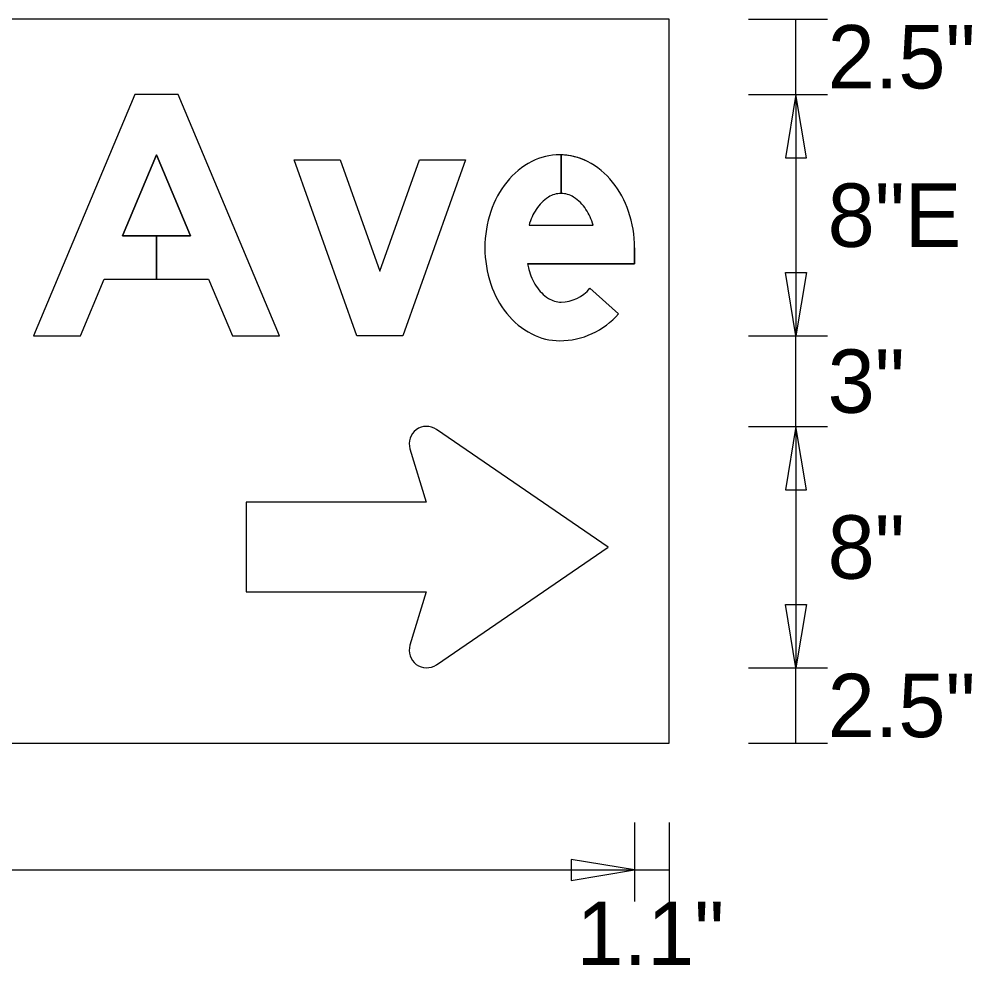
# Model space of a CAD drawing. Extents: x 1374 to 1480, y 568 to 638.
# Drawn here: x 1422.063 to 1424.694, y 629.461 to 632.074 of the extents above; entities that cross this region are included whole.
import ezdxf

# ---------------------------------------------------------------- set-up
doc = ezdxf.new("R2010")
doc.units = 0
for name, color, linetype in [('GSBWFill', 7, 'Continuous'), ('GSColorFill', 7, 'Continuous'), ('GSDims', 7, 'Continuous'), ('GSOutline', 7, 'Continuous')]:
    doc.layers.add(name, color=color, linetype=linetype)

msp = doc.modelspace()

# ---------------------------------------------------------------- linework, layer by layer
at = {"layer": 'GSBWFill'}
for p, q in [((1423.8581, 632.074), (1414.8581, 632.074)), ((1423.8581, 630.074), (1423.8581, 632.074)), ((1423.5594, 631.6989), (1423.5594, 631.5923)), ((1423.5594, 631.5923), (1423.5594, 631.6989)), ((1423.471, 631.5049), (1423.6478, 631.5049)), ((1423.6389, 631.3303), (1423.7184, 631.2601)), ((1414.8581, 630.074), (1423.8581, 630.074))]:
    msp.add_line(p, q, dxfattribs=at)
for points in [[(1422.5359, 631.4756), (1422.4423, 631.4756), (1422.4423, 631.3556), (1422.5863, 631.3556), (1422.6521, 631.199), (1422.7823, 631.199), (1422.5023, 631.8656), (1422.3823, 631.8656), (1422.1023, 631.199), (1422.2324, 631.199), (1422.2982, 631.3556), (1422.4423, 631.3556), (1422.4423, 631.4756), (1422.3486, 631.4756), (1422.4423, 631.6986)], [(1422.8223, 631.6856), (1422.9497, 631.6856), (1423.059, 631.3781), (1423.1683, 631.6856), (1423.2956, 631.6856), (1423.1226, 631.199), (1422.9953, 631.199)]]:
    msp.add_lwpolyline(points, close=True, dxfattribs=at)
for points in [[(1423.7623, 631.4423), (1423.7623, 631.3983), (1423.4665, 631.3983)], [(1423.2153, 630.2908), (1423.6899, 630.6157), (1423.2153, 630.9406)], [(1423.1421, 630.8868), (1423.1874, 630.7394), (1422.6899, 630.7394)], [(1422.6899, 630.7394), (1422.6899, 630.492), (1423.1874, 630.492), (1423.1421, 630.3446)]]:
    msp.add_lwpolyline(points, dxfattribs=at)
for centre, start, end in [((1423.1881, 630.9009), 55.6003, 197.0573), ((1423.1881, 630.3305), 162.9427, 304.3997)]:
    msp.add_arc(centre, 0.0481, start, end, dxfattribs=at)
for centre, major_axis, start_param, end_param in [((1423.5777, 631.4884), (0, 0.216), 0.475122, 0.892896), ((1423.5556, 631.5313), (0, 0.1677), 0, 0.475122), ((1423.5556, 631.5313), (0, 0.1677), 6.260763, 6.283185), ((1423.5556, 631.5313), (0, 0.1677), 5.808063, 6.260564), ((1423.5335, 631.4884), (0, 0.216), 5.390289, 5.808063), ((1423.6123, 631.4605), (0, 0.2604), 0.892896, 1.248875), ((1423.4989, 631.4605), (0, 0.2604), 5.03431, 5.390289), ((1423.5856, 631.487), (0, 0.113), 0.569258, 0.99633), ((1423.5594, 631.5279), (0, 0.0644), 0, 0.569258), ((1423.5594, 631.5279), (0, 0.0644), 5.713928, 6.282667), ((1423.5332, 631.487), (0, 0.113), 5.286855, 5.713928), ((1423.6273, 631.46), (0, 0.1627), 0.99633, 1.290964), ((1423.4915, 631.46), (0, 0.1627), 4.992222, 5.286855), ((1423.6668, 631.4423), (0, 0.3178), 1.248875, 1.570796), ((1423.4445, 631.4423), (0, 0.3178), 4.712389, 5.03431), ((1423.6668, 631.4423), (0, 0.3178), 1.570796, 1.892717), ((1423.6932, 631.4423), (0, 0.2309), 1.762764, 1.832751), ((1423.6273, 631.4246), (0, 0.1627), 1.832751, 2.145263), ((1423.6123, 631.4242), (0, 0.2604), 1.892717, 2.248697), ((1423.5856, 631.3977), (0, 0.113), 2.145263, 2.572335), ((1423.5594, 631.3946), (0, 0.1022), 3.141593, 4.032312), ((1423.5594, 631.3567), (0, 0.0644), 2.572335, 3.141593), ((1423.5777, 631.3963), (0, 0.216), 2.248697, 2.666471), ((1423.5556, 631.4007), (0, 0.2151), 3.141593, 3.999873), ((1423.5556, 631.3533), (0, 0.1677), 2.666471, 3.141593)]:
    msp.add_ellipse(centre, major_axis=major_axis, ratio=0.999992, start_param=start_param, end_param=end_param, dxfattribs=at)
at = {"layer": 'GSColorFill'}
for p, q in [((1423.8581, 632.074), (1414.8581, 632.074)), ((1423.8581, 632.074), (1414.8581, 632.074)), ((1423.8581, 630.074), (1423.8581, 632.074)), ((1423.8581, 630.074), (1423.8581, 632.074)), ((1423.5594, 631.6989), (1423.5594, 631.5923)), ((1423.5594, 631.5923), (1423.5594, 631.6989)), ((1423.471, 631.5049), (1423.6478, 631.5049)), ((1423.6389, 631.3303), (1423.7184, 631.2601)), ((1414.8581, 630.074), (1423.8581, 630.074)), ((1414.8581, 630.074), (1423.8581, 630.074))]:
    msp.add_line(p, q, dxfattribs=at)
for points in [[(1422.5359, 631.4756), (1422.4423, 631.4756), (1422.4423, 631.3556), (1422.5863, 631.3556), (1422.6521, 631.199), (1422.7823, 631.199), (1422.5023, 631.8656), (1422.3823, 631.8656), (1422.1023, 631.199), (1422.2324, 631.199), (1422.2982, 631.3556), (1422.4423, 631.3556), (1422.4423, 631.4756), (1422.3486, 631.4756), (1422.4423, 631.6986)], [(1422.8223, 631.6856), (1422.9497, 631.6856), (1423.059, 631.3781), (1423.1683, 631.6856), (1423.2956, 631.6856), (1423.1226, 631.199), (1422.9953, 631.199)]]:
    msp.add_lwpolyline(points, close=True, dxfattribs=at)
for points in [[(1423.7623, 631.4423), (1423.7623, 631.3983), (1423.4665, 631.3983)], [(1423.2153, 630.2908), (1423.6899, 630.6157), (1423.2153, 630.9406)], [(1423.1421, 630.8868), (1423.1874, 630.7394), (1422.6899, 630.7394)], [(1422.6899, 630.7394), (1422.6899, 630.492), (1423.1874, 630.492), (1423.1421, 630.3446)]]:
    msp.add_lwpolyline(points, dxfattribs=at)
for centre, start, end in [((1423.1881, 630.9009), 55.6003, 197.0573), ((1423.1881, 630.3305), 162.9427, 304.3997)]:
    msp.add_arc(centre, 0.0481, start, end, dxfattribs=at)
for centre, major_axis, start_param, end_param in [((1423.5777, 631.4884), (0, 0.216), 0.475122, 0.892896), ((1423.5556, 631.5313), (0, 0.1677), 0, 0.475122), ((1423.5556, 631.5313), (0, 0.1677), 6.260763, 6.283185), ((1423.5556, 631.5313), (0, 0.1677), 5.808063, 6.260564), ((1423.5335, 631.4884), (0, 0.216), 5.390289, 5.808063), ((1423.6123, 631.4605), (0, 0.2604), 0.892896, 1.248875), ((1423.4989, 631.4605), (0, 0.2604), 5.03431, 5.390289), ((1423.5856, 631.487), (0, 0.113), 0.569258, 0.99633), ((1423.5594, 631.5279), (0, 0.0644), 0, 0.569258), ((1423.5594, 631.5279), (0, 0.0644), 5.713928, 6.282667), ((1423.5332, 631.487), (0, 0.113), 5.286855, 5.713928), ((1423.6273, 631.46), (0, 0.1627), 0.99633, 1.290964), ((1423.4915, 631.46), (0, 0.1627), 4.992222, 5.286855), ((1423.6668, 631.4423), (0, 0.3178), 1.248875, 1.570796), ((1423.4445, 631.4423), (0, 0.3178), 4.712389, 5.03431), ((1423.6668, 631.4423), (0, 0.3178), 1.570796, 1.892717), ((1423.6932, 631.4423), (0, 0.2309), 1.762764, 1.832751), ((1423.6273, 631.4246), (0, 0.1627), 1.832751, 2.145263), ((1423.6123, 631.4242), (0, 0.2604), 1.892717, 2.248697), ((1423.5856, 631.3977), (0, 0.113), 2.145263, 2.572335), ((1423.5594, 631.3946), (0, 0.1022), 3.141593, 4.032312), ((1423.5594, 631.3567), (0, 0.0644), 2.572335, 3.141593), ((1423.5777, 631.3963), (0, 0.216), 2.248697, 2.666471), ((1423.5556, 631.4007), (0, 0.2151), 3.141593, 3.999873), ((1423.5556, 631.3533), (0, 0.1677), 2.666471, 3.141593)]:
    msp.add_ellipse(centre, major_axis=major_axis, ratio=0.999992, start_param=start_param, end_param=end_param, dxfattribs=at)
at = {"layer": 'GSDims'}
for p, q in [((1424.0769, 632.074), (1424.2956, 632.074)), ((1424.0769, 632.074), (1424.0769, 632.074)), ((1424.2081, 631.8656), (1424.2081, 632.074)), ((1424.0769, 631.8656), (1424.2956, 631.8656)), ((1424.0769, 631.8656), (1424.2956, 631.8656)), ((1424.2081, 631.8656), (1424.2081, 631.199)), ((1424.0769, 631.199), (1424.2956, 631.199)), ((1424.0769, 631.199), (1424.2956, 631.199)), ((1424.2081, 630.949), (1424.2081, 631.199)), ((1424.0769, 630.949), (1424.2956, 630.949)), ((1424.0769, 630.949), (1424.2956, 630.949)), ((1424.2081, 630.949), (1424.2081, 630.2824)), ((1424.0769, 630.2824), (1424.2956, 630.2824)), ((1424.0769, 630.2824), (1424.2956, 630.2824)), ((1424.2081, 630.074), (1424.2081, 630.2824)), ((1424.0769, 630.074), (1424.2956, 630.074)), ((1424.0769, 630.074), (1424.0769, 630.074)), ((1423.7623, 629.8552), (1423.7623, 629.6365)), ((1423.7623, 629.8552), (1423.7623, 629.6365)), ((1423.8581, 629.8552), (1423.8581, 629.6365)), ((1423.8581, 629.8552), (1423.8581, 629.6365)), ((1414.9553, 629.724), (1423.7623, 629.724)), ((1423.7623, 629.724), (1423.8581, 629.724))]:
    msp.add_line(p, q, dxfattribs=at)
for points in [[(1424.2081, 631.8656), (1424.179, 631.6906), (1424.2373, 631.6906)], [(1424.2081, 631.199), (1424.179, 631.374), (1424.2373, 631.374)], [(1424.2081, 630.949), (1424.179, 630.774), (1424.2373, 630.774)], [(1424.2081, 630.2824), (1424.179, 630.4574), (1424.2373, 630.4574)], [(1423.7623, 629.724), (1423.5873, 629.7531), (1423.5873, 629.6948)]]:
    msp.add_lwpolyline(points, close=True, dxfattribs=at)
at = {"layer": 'GSOutline'}
for p, q in [((1423.8581, 632.074), (1414.8581, 632.074)), ((1423.8581, 630.074), (1423.8581, 632.074)), ((1423.471, 631.5049), (1423.6478, 631.5049)), ((1423.7184, 631.2601), (1423.6389, 631.3303)), ((1414.8581, 630.074), (1423.8581, 630.074))]:
    msp.add_line(p, q, dxfattribs=at)
for points in [[(1422.2982, 631.3556), (1422.5863, 631.3556), (1422.6521, 631.199), (1422.7823, 631.199), (1422.5023, 631.8656), (1422.3823, 631.8656), (1422.1023, 631.199), (1422.2324, 631.199)], [(1422.5359, 631.4756), (1422.4423, 631.6986), (1422.3486, 631.4756)], [(1422.8223, 631.6856), (1422.9497, 631.6856), (1423.059, 631.3781), (1423.1683, 631.6856), (1423.2956, 631.6856), (1423.1226, 631.199), (1422.9953, 631.199)]]:
    msp.add_lwpolyline(points, close=True, dxfattribs=at)
for points in [[(1423.4665, 631.3983), (1423.7623, 631.3983), (1423.7623, 631.4423)], [(1423.2153, 630.2908), (1423.6899, 630.6157), (1423.2153, 630.9406)], [(1423.1421, 630.8868), (1423.1874, 630.7394), (1422.6899, 630.7394)], [(1422.6899, 630.7394), (1422.6899, 630.492), (1423.1874, 630.492), (1423.1421, 630.3446)]]:
    msp.add_lwpolyline(points, dxfattribs=at)
for centre, start, end in [((1423.1881, 630.9009), 55.6003, 197.0573), ((1423.1881, 630.3305), 162.9427, 304.3997)]:
    msp.add_arc(centre, 0.0481, start, end, dxfattribs=at)
for centre, major_axis, start_param, end_param in [((1423.5777, 631.4884), (0, 0.216), 0.475122, 0.892896), ((1423.5556, 631.5313), (0, 0.1677), 0, 0.475122), ((1423.5556, 631.5313), (0, 0.1677), 5.808063, 6.283185), ((1423.5335, 631.4884), (0, 0.216), 5.390289, 5.808063), ((1423.6123, 631.4605), (0, 0.2604), 0.892896, 1.248875), ((1423.4989, 631.4605), (0, 0.2604), 5.03431, 5.390289), ((1423.5856, 631.487), (0, 0.113), 0.569258, 0.99633), ((1423.5594, 631.5279), (0, 0.0644), 0, 0.569258), ((1423.5594, 631.5279), (0, 0.0644), 5.713928, 6.283185), ((1423.5332, 631.487), (0, 0.113), 5.286855, 5.713928), ((1423.6273, 631.46), (0, 0.1627), 0.99633, 1.290964), ((1423.4915, 631.46), (0, 0.1627), 4.992222, 5.286855), ((1423.6668, 631.4423), (0, 0.3178), 1.248875, 1.570796), ((1423.4445, 631.4423), (0, 0.3178), 4.712389, 5.03431), ((1423.6668, 631.4423), (0, 0.3178), 1.570796, 1.892717), ((1423.6932, 631.4423), (0, 0.2309), 1.762763, 1.832751), ((1423.6273, 631.4246), (0, 0.1627), 1.832751, 2.145263), ((1423.6123, 631.4242), (0, 0.2604), 1.892717, 2.248697), ((1423.5856, 631.3977), (0, 0.113), 2.145263, 2.572335), ((1423.5594, 631.3946), (0, 0.1022), 3.141593, 4.032312), ((1423.5594, 631.3567), (0, 0.0644), 2.572335, 3.141593), ((1423.5777, 631.3963), (0, 0.216), 2.248697, 2.666471), ((1423.5556, 631.4007), (0, 0.2151), 3.141593, 3.999873), ((1423.5556, 631.3533), (0, 0.1677), 2.666471, 3.141593)]:
    msp.add_ellipse(centre, major_axis=major_axis, ratio=0.999992, start_param=start_param, end_param=end_param, dxfattribs=at)

# ---------------------------------------------------------------- texts
at = {"layer": 'GSDims'}
for s, p in [('2.5"', (1424.2956, 631.8823)), ('8"E', (1424.2956, 631.4448)), ('3"', (1424.2956, 630.9865)), ('8"', (1424.2956, 630.5282)), ('2.5"', (1424.2956, 630.0907)), ('1.1"', (1423.6019, 629.4615))]:
    msp.add_text(s, height=0.175, dxfattribs=at).set_placement(p)

doc.saveas('drawing.dxf')
